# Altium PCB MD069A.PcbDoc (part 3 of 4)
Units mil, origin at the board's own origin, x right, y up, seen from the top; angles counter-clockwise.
Board outline 4569 x 3239 mil, 4 copper layers (Top Layer, Signal Layer 1, Signal Layer 2, Bottom Layer), stack 61.2 mil thick; 187 components, 103 nets, 560 pads, 220 vias.
Unrouted connection lines stored in the file: 7.
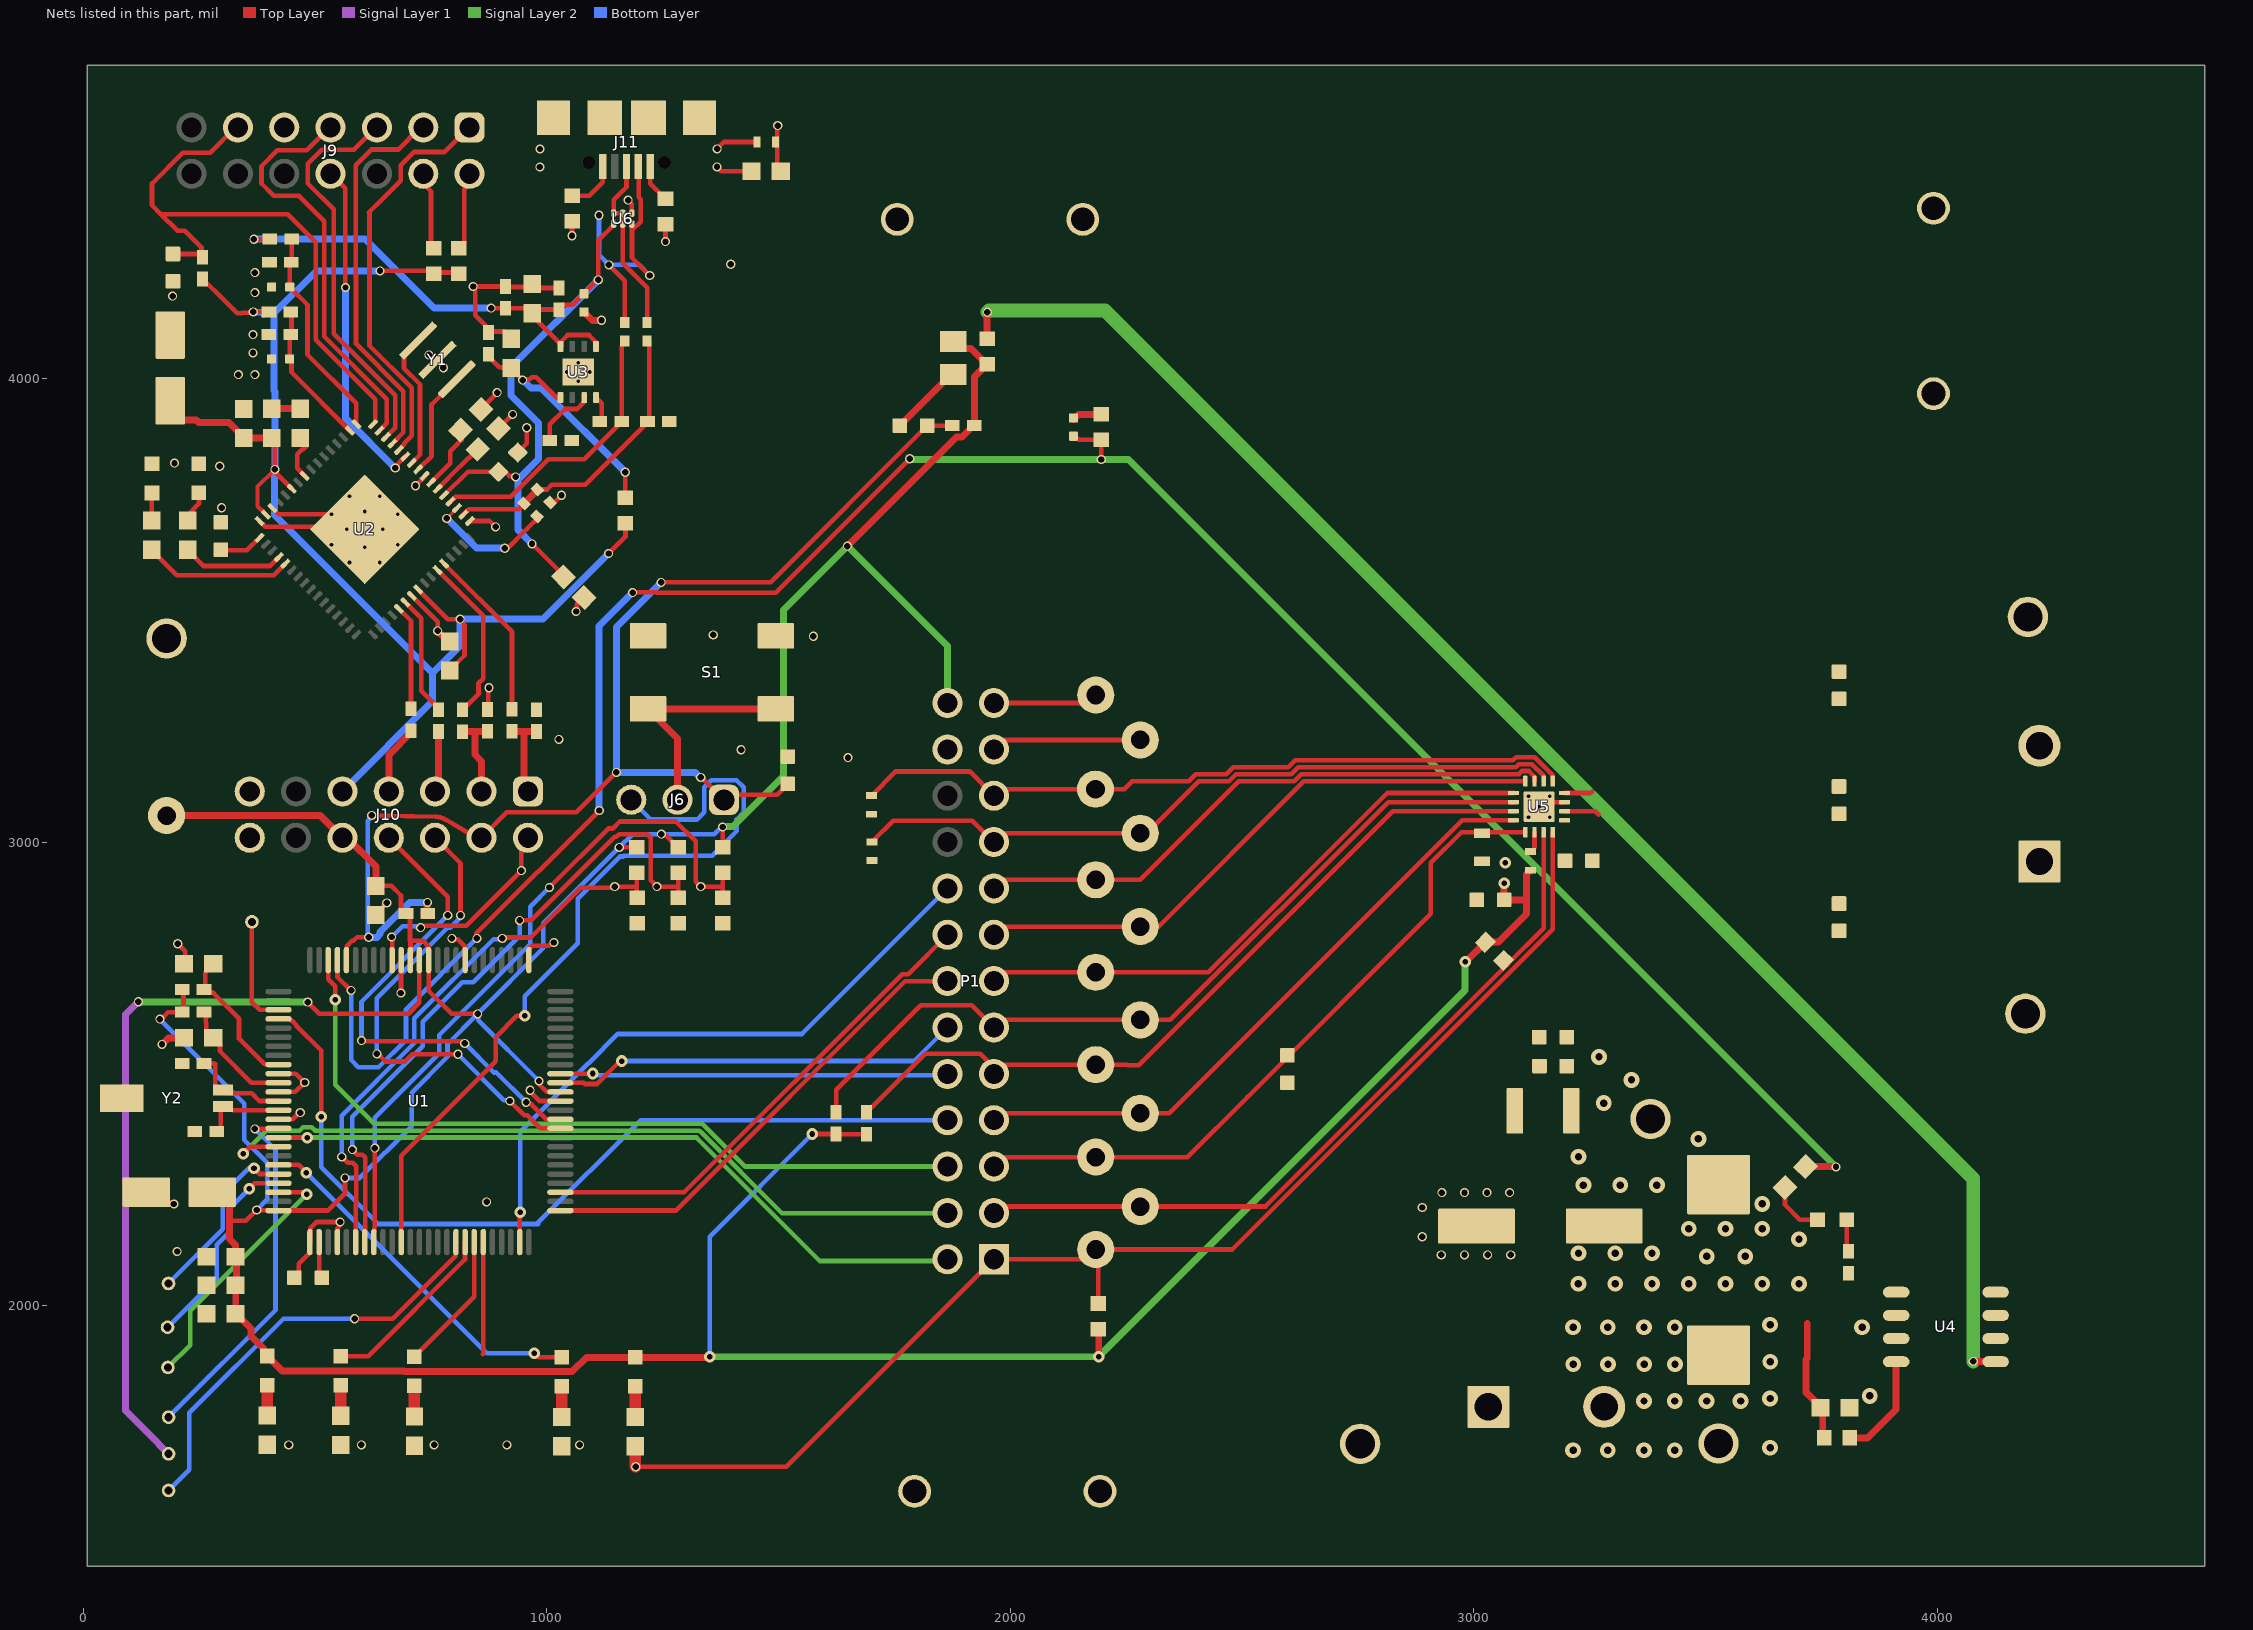
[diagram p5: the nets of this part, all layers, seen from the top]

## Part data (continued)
R58: library part CMP-0025924-5, "RES, 470, 5%, 0.1 W, 0603", Manufacturer=Yageo, Power_W=100mW, Supplier Part Number 1=311-470GRCT-ND, TempCo="100 ppm/C", Tolerance_%=5%, Value2=0.1W, Value_Code=470R, ValueDisplayed=470
R61: library part CMP-0026021-3, "RES, 150 k, 1%, 0.063 W, AEC-Q200 Grade 0, 0402", Manufacturer=Vishay-Dale, Power_W=63mW, Supplier Part Number 1=541-150KLCT-ND, TempCo="100 ppm/C", Tolerance_%=1%, Value2=0.063W, Value_Code=150k
R72 R75: library part CMP-0026888-3, "RES, 27, 5%, 0.063 W, AEC-Q200 Grade 0, 0402", Manufacturer=Vishay-Dale, Power_W=63mW, Supplier Part Number 1=541-27JCT-ND, TempCo="200 ppm/C", Tolerance_%=5%, Value2=0.063W, Value_Code=27R0, ValueDisplayed=27
R76: library part CMP-0026085-3, "RES, 1.40 k, 1%, 0.063 W, AEC-Q200 Grade 0, 0402", Manufacturer=Vishay-Dale, Power_W=63mW, Supplier Part Number 1=541-1.40KLCT-ND, TempCo="100 ppm/C", Tolerance_%=1%, Value2=0.063W, Value_Code=1k40, ValueDisplayed=1.40k
R77: library part CMP-0026859-2, "RES, 1.0 M, 5%, 0.063 W, AEC-Q200 Grade 0, 0402", Manufacturer=Vishay-Dale, Power_W=63mW, Supplier Part Number 1=541-1.0MJCT-ND, TempCo="200 ppm/C", Tolerance_%=5%, Value2=0.063W, Value_Code=1M00, ValueDisplayed=1.0M
R78: library part CMP-0026907-3, "RES, 33 k, 5%, 0.063 W, AEC-Q200 Grade 0, 0402", Manufacturer=Vishay-Dale, Power_W=63mW, Supplier Part Number 1=541-33KJCT-ND, TempCo="200 ppm/C", Tolerance_%=5%, Value2=0.063W, Value_Code=33k0, ValueDisplayed=33k
S1: library part CMP-0097347-1, "Tactile Switch SPST-NO Top Actuated Surface Mount", Coil Resistance_ohm=100mΩ, Contact Current Rating=50mA, Digikey Part Number=732-7022-1-ND, Manufacturer="Wurth Electronics", Mouser Part Number=710-430481025816, Operating Force=160gf, Operating Temperature Range="-40°C to +85°C"
SH-J1 SH-J2 SH-J3 SH-J4 SH-J5 SH-J6 SH-J7 SH-J8 SH-J9 SH-J10 SH-J11 SH-J12 SH-J19 SH-J29 SH-J31 SH-J32 SH-J33 SH-J34 SH-J36: library part CMP-0003761-2, "Shunt, 2.54mm, Gold, Black", Manufacturer="Wurth Elektronik", Supplier Part Number 1=732-2678-ND
TP1 TP2 TP3 TP4 TP5 TP6 TP7: library part CMP-0003719-1, "Testpoint", Manufacturer="Texas Instruments"
TP8 TP10: library part CMP-0055149-2, "Test Point, Multipurpose, White, TH", Color=White, Manufacturer="Keystone Electronics", Supplier Part Number 1=36-5012-ND
TP16 TP17 TP60: library part CMP-0075110-1, "1mm Uninsulated Shorting Plug, 10.16mm spacing, TH", Manufacturer=Harwin, PartNumber=D3082-05, Supplier Part Number 1=952-1873-ND
TP26: library part CMP-0055140-2, "Test Point, Miniature, Orange, TH", Color=Orange, Manufacturer="Keystone Electronics", Supplier Part Number 1=36-5003-ND
TP28 TP29 TP30 TP31 TP32 TP33 TP34 TP35 TP36 TP37 TP38 TP39 TP40: library part CMP-0055139-2, "Test Point, Miniature, White, TH", Color=White, Manufacturer="Keystone Electronics", Supplier Part Number 1=36-5002-ND
U1: library part CMP-0038879-1, "20 MHz Mixed Signal Microcontroller with 256 KB Flash, 18432 B SRAM and 74 GPIOs, -40 to 85 degC, 100-pin QFP (PZ), Green (RoHS & no Sb/Br)", Frequency(MHz)=20, Manufacturer="Texas Instruments", Temp Sensor=Yes
U2: library part CMP-0039269-4, "16-Bit Ultra-Low-Power Microcontroller, 128KB Flash, 8KB RAM, USB, 12Bit ADC, 2 USCIs, 32Bit HW MPY, RGC0064B (VQFN-64)", Alternate Manufacturer="Texas Instruments", Alternate PartNumber=MSP430F5528IRGCR, Frequency(MHz)=25, Operating Temperature Range="-40 to 85 C", Rating=Catalog, Temp Sensor=Yes
U3: library part CMP-0036328-3, "500mA, Adjustable, Low Quiescent Current, Low-Noise, High-PSRR, Single-Output LDO Regulator, DRB0008A (VSON-8)", Manufacturer="Texas Instruments", Operating Temperature Range="-40 to 125 C", Rating=Catalog
U4: library part CMP-0070570-1, "Ultra-Low Quiescent Current Voltage Regulator, 8-pin Narrow SOIC, Pb-Free", Manufacturer="Texas Instruments", PackageTopMarking=NSZXTT*LM903*6M-3, PowerWise=N
U5: library part CMP-0097573-1, "2-A Brushed DC Motor Driver with Stall Detection, Ripple Counting and Speed Regulation", Manufacturer="Texas Instruments", Max Supply Voltage=11V, Min Supply Voltage=1.65V, Operating Temperature Range="-40°C to +150°C", Switching Frequency=200kHz
U6: library part CMP-0043099-3, "Low-Capacitance 2-Channel +/-15kV ESD Protection Array for High-Speed Data Interfaces, DRY0006A (USON-6)", Breakdown Voltage(Min)(V)=11, IO Capacitance(Typ)(pF)=1.5, IO Leakage Current(nA)=1, Manufacturer="Texas Instruments", Operating Temperature Range="-40 to 85 C", Rating=Catalog
VM VSUP: library part CMP-0055147-2, "Test Point, Multipurpose, Red, TH", Color=Red, Manufacturer="Keystone Electronics", Supplier Part Number 1=36-5010-ND
Y1: library part CMP-0085483-1, "Oscillator, 4 MHz, 700 ppm, 39 pF, SMD", Frequency_Fixed=4MHz, Frequency Tolerance="700 ppm", Load Capacitance="39 pF", Manufacturer=MuRata
Y2: library part CMP-0004566-4, "Crystal, 32.768 kHz, 12.5pF, SMD", Alternate Manufacturer="Wurth Electronics", Alternate PartNumber=830025159, Frequency Tolerance="20 ppm", Frequency_Fixed=32.768kHz, Load Capacitance="12.5 pF", Manufacturer="Micro Crystal AG", Supplier Part Number 1=94M8466
ZZ1: library part CMP-0077236-1
ZZ2: library part CMP-0077237-1
ZZ3: library part CMP-0077238-1
ZZ4: library part CMP-0003616-3

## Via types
v1: diameter 19.68, hole 13.78, Top Layer to Bottom Layer, tented both sides, 133 vias
v2: diameter 34, hole 16, Top Layer to Bottom Layer, tented both sides, 47 vias
v3: diameter 25/25/25/25 (per signal layer), hole 12, Top Layer to Bottom Layer, 19 vias
v4: diameter 19.68, hole 7.87, Top Layer to Bottom Layer, 16 vias
v5: diameter 19.68, hole 7.87, Top Layer to Bottom Layer, tented both sides, 5 vias

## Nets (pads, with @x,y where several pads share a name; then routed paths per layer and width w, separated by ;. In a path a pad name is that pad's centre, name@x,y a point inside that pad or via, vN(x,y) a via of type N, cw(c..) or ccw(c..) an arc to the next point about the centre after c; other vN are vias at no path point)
A0: P1.19 R8.2 TP37.1 U5.10 | length 1579.1
  Top Layer w10: R8.2@1701.01,3000.93 1747.05,3046.97 1918.02,3046.97 P1.19@1964.3,3000.7 1983.33,3019.73 TP37.1@2280.18,3019.73 2293.85,3019.73 2406.28,3132.17 2471.63,3132.17 2486.63,3147.17 2605.79,3147.17 2620.79,3162.17 3090.2,3162.17 3097.01,3168.98 3124.85,3168.98 3150.3,3143.53 U5.10@3150.3,3132.17
A1: P1.21 R10.2 TP38.1 U5.9 | length 1576.2
  Top Layer w10: R10.2@1700.67,3100.69 1753.06,3153.07 1911.92,3153.07 P1.21@1964.3,3100.7 1978.49,3114.89 TP38.1@2183.57,3114.89 2245.13,3114.89 2262.41,3132.17 2385.07,3132.17 2400.07,3147.17 2465.42,3147.17 2480.42,3162.17 2599.57,3162.17 2614.57,3177.17 3083.99,3177.17 3090.8,3183.98 3131.06,3183.98 3169.98,3145.05 U5.9@3169.98,3132.17
ENABLE: U1.45 | length 242.7
  Top Layer w10: 862.05,1895.51 862.95,1896.41 U1.45@862.95,2137.87
EZFET_AVBUS: C24.2 R56.1 R61.2 U2.1 | length 460.2
  Top Layer w10: R56.1@449.36,4301.26 449.36,4251.97 445.4,4248.02 C24.2@445.4,4197.93 483.64,4159.68 483.64,4052.32 588.83,3947.13 U2.1@588.83,3902.1
EZFET_AVCC2ADC: C22.2 R55.1 R60.2 U2.2 | length 312.5
  Top Layer w10: R55.1@447.69,4144.57 449.02,4143.24 449.02,4096.99 444.96,4092.94 C22.2@444.96,4043.12 449.02,4039.07 449.02,4014.07 U2.2@574.91,3888.18
EZFET_D_N: C42.1 R72.2 U2.52 | length 613.9
  Top Layer w10: U2.52@792.05,3735.07 802.99,3746 922.1,3746 1002.59,3826.49 1080.35,3826.49 C42.1@1161.52,3907.66 1161.52,4071.53 R72.2@1167.94,4077.95
EZFET_D_P: C43.1 R75.2 R76.1 R77.2 U2.50 | length 662.5
  Top Layer w10: U2.50@819.89,3707.23 831.67,3719 939,3719 R76.1@951,3731 ; R77.2@979.43,3761.27 1000.2,3761.27 1010.57,3771.64 1082.64,3771.64 C43.1@1220,3909 ; R75.2@1216,4083 1221.01,4077.99 C43.1@1221.01,3907.66
  Top Layer w15: R76.1@950.97,3731.25 979,3759.28 R77.2@979,3762
EZFET_LED0: R58.1 U2.20 | length 219.7
  Top Layer w10: R58.1@225.05,3631.48 225.05,3630.5 259.15,3596.4 402.84,3596.4 U2.20@421.8,3615.36
EZFET_LED1: R59.1 U2.21 | length 322.2
  Top Layer w10: R59.1@147.47,3631.44 147.47,3630.46 201.82,3576.1 410.38,3576.1 U2.21@435.72,3601.44
EZFET_PUR: R76.2 U2.51 | length 282.9
  Top Layer w6: v1(784.09,3698.93) 805.97,3720.81 U2.51@805.97,3721.34
  Top Layer w10: v1(909,3634.64) 915.6,3634.64 957,3676.03 R76.2@981.59,3700.62
  Bottom Layer w15: v1(784.09,3698.93) 848.39,3634.64 v1(909,3634.64)
EZFET_RST: C23.2 J9.11 R57.1 U2.64 | length 1315.2
  Top Layer w10: C23.2@193.39,4269.42 250.7,4269.42 R57.1@257.39,4262.73 254.8,4265.32 254.8,4283.48 218.88,4319.4 203.25,4319.4 167.33,4355.31 ; J9.11@333.43,4542.4 328.31,4542.4 273.67,4487.76 214.64,4487.76 148.19,4421.31 148.19,4374.45 167.33,4355.31 ; U2.64@629.64,3907.11 629.64,3955.86 501.52,4083.99 501.52,4294.87 441.07,4355.31 167.33,4355.31
EZFET_TCK: J9.7 U2.63 | length 899.5
  Top Layer w10: J9.7@529.76,4540.24 482.32,4492.8 418.18,4492.8 384.4,4459.03 384.4,4421.46 410.97,4394.89 464.38,4394.89 519.39,4339.88 519.39,4091.39 654.78,3956 654.78,3904.22 U2.63@638.94,3888.38
EZFET_TDI: J9.3 U2.61 | length 820.7
  Top Layer w10: U2.61@671.5,3865.26 690.53,3884.29 690.53,3973.19 588.33,4075.39 588.33,4223.81 588.07,4224.06 588.07,4461.19 621.53,4494.65 679.2,4494.65 724.8,4540.24 J9.3@729.76,4540.24
EZFET_TDO: J9.1 U2.60 | length 870.4
  Top Layer w10: U2.60@680.7,3846.62 692.58,3858.51 692.58,3861.06 708.4,3876.89 708.4,3980.6 617.28,4071.72 617.28,4358.05 616.32,4359.01 646.16,4388.84 684.4,4427.09 684.4,4461.01 712.65,4489.26 778.77,4489.26 J9.1@829.76,4540.24
EZFET_TEST: J9.8 U2.59 | length 726
  Top Layer w10: J9.8@533.43,4442.4 565,4410.83 v1@565,4197 ; v1(672.79,3807.8) 672.79,3810.87 694.52,3832.6 U2.59@694.62,3832.7
  Bottom Layer w15: v1(565.61,4197) 565.61,3914.98 v1(672.79,3807.8)
EZFET_TMS: J9.5 U2.62 | length 852.8
  Top Layer w10: J9.5@629.76,4540.24 583.77,4494.26 514.42,4494.26 484.4,4464.23 484.4,4421.46 539.92,4365.94 539.92,4096.92 672.65,3964.19 672.65,3894.25 U2.62@652.86,3874.46
EZFET_UARTRXD: R66.1 U2.38 | length 254.2
  Top Layer w10: U2.38@699.43,3513.11 729.16,3483.38 729.16,3327.09 765.89,3290.36 R66.1@765.89,3286.42
EZFET_UARTTXD: R67.1 U2.37 | length 227
  Top Layer w10: U2.37@680.7,3504.2 706.91,3477.99 R67.1@706.91,3288
EZFET_USB_Shield: C47.1 J11.Shell R78.2 | length 181.9
  Top Layer w10: v1(1367,4457.41) 1376.38,4448.03 C47.1@1453,4448.03 ; v1(1367.15,4496.16) 1381.99,4511 R78.2@1453,4511
  other v1: 985,4457 985.15,4495.75
EZFET_V18: C28.1 U2.55 | length 140.3
  Top Layer w10: U2.55@750.29,3777.02 791.3,3817.94 791.3,3843.64 803,3855.34 815.89,3868.23 813.66,3870.46 C28.1@813.66,3889.21
EZFET_VBUS: C20.2 C21.1 C35.1 C36.1 C37.1 C48.2 L1.2 R56.2 U2.53 U3.5 U3.8 U6.1 | length 2228.6
  Top Layer w10: v1(367.89,4301.28) R56.2@398.15,4301.28 ; U2.53@778.13,3749.18 829.98,3799.33 910.6,3799.33 919.44,3790.49 930.76,3790.49 v1(932.61,3788.63) ; v1(879.84,4152.63) C35.1@907.4,4152.63 ; C35.1@910.39,4151.98 957.8,4151.98 C36.1@968.11,4141.67 969.17,4142.74 C36.1@974.92,4142.74 ; v1(967.96,3644) C21.1@1041.59,3570.37 ; U3.8@1029.31,4069.89 1030.41,4070.99 1030.41,4080.38 1044.61,4094.57 1090.78,4094.57 1104.98,4080.38 1104.98,4070.99 U3.5@1106.08,4069.89 ; U3.8@1029.31,4075.6 981.81,4123.1 981.81,4135.85 C36.1@974.92,4142.74 ; U6.1@1144.03,4334.75 1143.13,4333.85 1143.13,4330.89 1110.83,4298.6 v1(1110.83,4213.6) 1109.91,4213.6 1055.87,4159.56 1033.06,4159.56 1026.24,4152.75 C37.1@1026.24,4148.81 1025.51,4149.55 981.73,4149.55 C36.1@974.92,4142.74 ; v1(1255.92,4296.14) L1.2@1255.92,4329.25
  Bottom Layer w15: v1(367.89,4301.28) 607.38,4301.28 756.03,4152.63 v1(879.84,4152.63) ; v1(932.61,3788.63) v1@938.19,3783.05 ; v1(967.96,3644) 938.19,3673.77 v1@938.19,3783.05 ; v1(1110.83,4213.6) 922.39,4025.16 922.39,3964.54 981.9,3905.04 981.9,3826.76 v1@938.19,3783.05
EZFET_VCC: C31.2 C32.1 C33.1 C34.1 J10.9 R55.2 R57.2 R62.2 R63.2 R68.1 U2.11 U2.15 U2.40 | length 3248.3
  Top Layer w9: U2.15@393.96,3707.23 376.06,3725.12 376.06,3767.67 v1(413.25,3804.86)
  Top Layer w10: R57.2@257.39,4215.49 302.5,4170.38 303.28,4170.38 331.79,4141.87 341.79,4141.87 342.63,4142.72 364.73,4142.72 v1(366.58,4144.57) R55.2@396.5,4144.57 ; v1(413.25,3804.86) C32.1@413.25,3872.61 ; v1@415.1,3797.44 U2.11@449.63,3762.9 ; v1(640,4233) 749.76,4233 R62.2@756.08,4226.68 756.65,4226.11 761.71,4226.11 765.13,4229.53 806.74,4229.53 R63.2@809.84,4226.43 ; U2.40@727.27,3540.94 786.47,3481.74 v1(812.86,3481.74) 812.86,3479.12 822.29,3469.69 822.29,3403.19 C34.1@793.67,3374.56 ; v1@1133.28,3623.53 1169.5,3659.74 R68.1@1169.5,3688.8
  Top Layer w15: C31.2@187.54,3952.77 187.54,3934.97 211.54,3910.97 243.64,3910.97 249.04,3905.57 313.95,3905.57 346.36,3873.16 C33.1@346.36,3872.17 346.58,3872.39 406.29,3872.39 C32.1@406.51,3872.61
  Bottom Layer w15: v1(366.58,4144.57) 367.48,4143.68 385.62,4143.68 388.91,4140.38 390.4,4141.87 411.61,4141.87 ; v1@412.19,3804.86 412.19,3706.59 753.69,3365.09 ; v1(413.25,3804.86) 413.25,3973.18 411.61,3974.82 411.61,4141.87 ; J10.9@559,3110.02 753.69,3304.71 753.69,3365.09 ; v1(640,4233) 502.74,4233 411.61,4141.87 ; v1(1133.28,3623.24) 991.78,3481.74 v1(812.86,3481.74) 812.86,3424.26 753.69,3365.09
EZFET_Vcore: C29.2 U2.17 | length 94.9
  Top Layer w10: C29.2@296.85,3631.18 297.95,3630.07 353,3630.07 U2.17@380.04,3657.12
EZFET_VREF: C25.1 U2.9 | length 104.8
  Top Layer w10: C25.1@467.95,3872.61 481.65,3858.91 481.65,3856 482.35,3855.3 474.81,3847.76 472.01,3847.76 461.42,3837.17 461.42,3806.8 U2.9@477.47,3790.74
EZFET_VUSB: C30.1 U2.54 | length 121.4
  Top Layer w10: U2.54@764.21,3763.1 812.07,3810.87 C30.1@850.84,3848.16
EZFET_XT2IN: U2.57 Y1.1 | length 222.2
  Top Layer w10: U2.57@727.27,3809.48 751.21,3833.42 751.21,3944.62 Y1.1@805.78,3999.19
EZFET_XT2OUT: U2.58 Y1.3 | length 298.5
  Top Layer w10: U2.58@708.54,3818.58 708.54,3818.97 726.28,3836.71 726.28,3988 691.64,4022.64 691.64,4052.08 Y1.3@722.26,4082.7
GND: C1.1 C2.1 C3.1 C4.1 C6.2 C7.2 C8.1 C15.2 C20.1 C21.2 C22.1 C23.1 C24.1 C25.2 C26.1 C27.1 C28.2 C29.1 C30.2 C31.1 C32.2 C33.2 C34.2 C35.2 C36.2 C37.2 C38.2 C39.2 C40.2 C41.1 C42.2 C43.2 C44.1 C45.2 C46.1 C47.2 C48.1 C49.1 C50.2 C51.1 C52.2 C53.2 C54.2 C55.2 C56.1 C57.1 C58.1 C59.1 C60.1 D1.1 D2.1 GND.1 J8.1 J9.9 J10.13 J10.14 L2.2 P1.24 R2.2 R8.1 R10.1 R11.1 R35.1 R42.1 R43.1 R45.1 R47.1 R51.2 R52.2 R53.2 R60.1 R61.1 R77.1 R78.1 S1.3 S1.4 TP16.1 TP16.2 TP17.1 TP17.2 TP24.1 TP60.1 TP60.2 U1.10 U1.12 U1.15 U1.26 U1.29 U1.63 U1.76 U1.83 U1.90 U2.14 U2.16 U2.39 U2.49 U2.56 U2.65 U3.4 U3.9 U4.2 U4.3 U4.4 U4.5 U4.6 U4.7 U5.7 U5.17 U6.4 Y1.2 Y2.3 | length 2757.2
  Top Layer w10: v1(203.63,2781.31) 220.06,2764.88 C15.2@220.06,2738.54 ; U2.16@380.04,3693.31 392.35,3681 507,3681 U2.65@534,3708 ; U2.14@407.88,3721.15 420,3709.02 421,3708 U2.65@534,3708 ; U1.15@421.02,2402.63 421.37,2402.98 451.36,2402.98 465.38,2417 v1(468,2417) ; U1.12@421.02,2461.69 457.48,2461.69 v1(477.73,2481.94) 458.62,2501.06 U1.10@421.02,2501.06 ; C49.1@455.41,2060.9 464.6,2070.09 464.6,2090.89 488.35,2114.64 488.35,2137.27 489.28,2138.21 489.28,2167.72 502.56,2181 v1(554,2181) 552.15,2179.15 552.15,2171.53 548.34,2167.72 548.34,2138.21 U1.29@547.99,2137.87 ; U2.65@536,3708 U2.65@534,3708 ; C54.2@630.92,2851.07 636.2,2851.07 v1(654.65,2869.51) ; v1(685,2675) 685.44,2675.44 685.44,2745.79 U1.90@685.79,2746.13 ; U2.39@708.54,3531.84 764.44,3475.94 v1(764.44,3456.19) ; v1(716.63,3769.36) 736.37,3789.11 U2.56@736.37,3790.94 ; v1(745.32,4051.62) 760.01,4036.93 763.94,4036.93 v1(776.82,4024.06) ; v1(795,2793) 796.85,2791.15 808.08,2791.15 823.24,2775.99 823.24,2746.48 U1.83@823.58,2746.13 ; U2.49@833.81,3693.31 876.77,3693.31 v1(889.43,3680.66) ; v1(840.84,4199.19) C35.2@910.39,4199.23 C35.2@910.39,4199.23 911.58,4198.04 966.86,4198.04 966.86,4203.42 C36.2@968.11,4204.66 968.11,4196.79 968.85,4196.05 C37.2@1026.24,4196.05 ; v1@845.32,4197.95 v1@845.32,4199.19 ; v1@845.35,4197.95 845.35,4137.48 873.88,4108.95 C40.2@873.88,4100.09 ; C28.2@852.64,3928.19 852.64,3930.14 v1(892.79,3970.29) ; C27.1@871.56,3286.62 873.62,3288.68 873.62,3332.09 v1(875.13,3333.6) ; C40.2@876.09,4102.3 908.06,4102.3 922.83,4087.54 C38.2@922.83,4086.55 ; C30.2@889.84,3887.12 v1(926.12,3923.39) ; C20.1@937.16,3841.09 956.69,3860.62 v1(956.69,3894.59) ; U1.76@961.38,2746.13 961.72,2746.48 961.72,2770.56 968.14,2776.98 1005.36,2776.98 1012.38,2784 v1(1015,2784) ; v1(963.9,2465.44) 963.9,2462.82 969.73,2456.98 969.73,2456.89 984.62,2442 U1.63@1029.29,2442 ; R77.1@1010.05,3730.65 1013.22,3730.65 v1(1031.49,3748.92) ; v1(1054.16,4308.62) 1054.16,4335.07 L2.2@1054.9,4335.81 ; v1(1063,3498) 1064.85,3499.85 1064.85,3513.9 1084,3533.04 C21.2@1084,3534 ; U3.4@1106.08,3959.65 1118,3947.73 C42.2@1118,3907 ; v1(1175.24,4385.46) 1183.4,4377.29 U6.4@1183.4,4357.39 ; C47.2@1496.62,4448.03 1496.62,4544.82 v1(1498,4546.19) ; v5(3140.46,3077.05) 3150.3,3086.89 U5.7@3195.57,3086.89
  Top Layer w15: C51.1@136.11,2245.41 160.11,2221.41 192.44,2221.41 193.99,2219.86 v1(195.25,2219.86) ; v1(169.75,2564.27) 183.73,2578.26 217,2578.26 C50.2@217.14,2578.4 ; C32.2@406.51,3935.6 C25.2@467.95,3935.6 ; v1(764.44,3456.19) 764.44,3455.96 C34.2@790.72,3429.68 ; C48.1@1080,4144.31 1097.99,4126.32 v1(1117.95,4126.32) ; C59.1@1768,3900 1768,3905.53 1855.7,3993.23 1855.7,3994.28 1873.72,4012.29 C7.2@1876.75,4012.29 ; C60.1@2136,3911.89 2147.11,3923 R35.1@2196,3923
  other v1: 443.05,1700.33 599.93,1700.33 756.8,1700.33 913.68,1700.33 1070.55,1700.33 2929.51,2110.26 2979.51,2110.26 3029.51,2110.26 3079.51,2110.26 202.42,2117.39 2888.51,2149.26 2888.51,2212.26 870.07,2224.49 2930.92,2244.53 2979.59,2244.53 3028.25,2244.53 3076.92,2244.53 1649.56,3182.96 1418.99,3199.88 1025.9,3222.11 1574.98,3444.66 1358.86,3447.68 298.25,3722.05 294.34,3811.53 196.74,3818.09 334.57,4009 370,4009 366.13,4056.01 366.13,4095.37 192.63,4178.37 370.07,4185.93 370.07,4229.24 1396.61,4247.27
  other v2: 3853.95,1805.95 3837.38,1954
  other v3: 3067.69,2955.69
  other v4: 574.07,3603.67 639.77,3603.67 606.92,3636.52 535.38,3642.36 678.47,3642.36 568.23,3675.21 645.62,3675.21 535.38,3708.06 678.47,3708.06 606.92,3713.91 574.07,3746.76 639.77,3746.76 1067.69,3995.09 1043.09,4014.77 1092.3,4014.77 1067.69,4034.46
  other v5: 3117.62,3054.22 3163.29,3054.22 3117.62,3099.88 3163.29,3099.88
GUI_STATUS: D8.2 U1.44 | length 298.6
  Top Layer w10: D8.2@719.51,1890.5 719.51,1895.74 843.27,2019.51 U1.44@843.27,2137.87
ID1: R39.2 R51.1 U1.31 | length 1220.2
  Top Layer w10: v1(557.56,2321.56) 570.59,2308.53 581.5,2308.53 588.72,2301.32 588.72,2220.59 587.36,2219.24 U1.31@587.36,2137.87 ; v1(903.72,2793) 905.57,2794.85 965.38,2794.85 1072.99,2902.47 1144.49,2902.47 v1(1146.5,2904.48) 1191.25,2904.48 1194.18,2907.41 ; R39.2@1194.18,2934.17 1194.18,2907.41 ; R51.1@1194.54,2880.29 1194.18,2880.65 1194.18,2907.41
  Bottom Layer w10: v1(557.56,2321.56) 557.56,2410.72 714.11,2567.26 714.11,2620.38 884.88,2791.15 901.86,2791.15 v1(903.72,2793)
ID2: R40.2 R52.1 U1.32 | length 1451
  Top Layer w10: v1(580.28,2337.17) 591.04,2326.41 602.09,2326.41 607.95,2320.55 607.95,2161.9 607.05,2160.99 U1.32@607.05,2137.87 ; v1(941.28,2831.72) 966.56,2831.72 1146.84,3012.01 1150.25,3012.01 1156.15,3017.91 1216.24,3017.91 1223.79,3010.37 1223.79,2918.04 v1(1237.35,2904.48) 1280.21,2904.48 1283.18,2907.45 ; R40.2@1283.18,2934.17 1283.18,2907.45 ; R52.1@1283.61,2880.29 1283.18,2880.72 1283.18,2907.45
  Bottom Layer w10: v1(580.28,2337.17) 580.28,2408.16 731.98,2559.86 731.98,2612.97 817.29,2698.28 841.13,2698.28 941.28,2798.44 v1(941.28,2831.72)
ID3: R41.2 R53.1 U1.33 | length 1518.9
  Top Layer w10: U1.33@626.73,2137.87 626.73,2160.99 627.64,2161.9 627.64,2168.28 628.86,2169.5 v1(628.86,2340.54) ; v1(1005.35,2902.65) 1132.59,3029.88 1142.28,3029.88 1157.51,3045.11 1278.05,3045.11 1321,3002.16 1321,2915.45 v1(1331.97,2904.48) 1376.41,2904.48 1379.34,2907.41 ; R41.2@1379.34,2934.17 1379.34,2907.41 ; R53.1@1379.69,2880.29 1379.34,2880.64 1379.34,2907.41
  Bottom Layer w10: v1(628.86,2340.54) 628.86,2406.03 767.73,2544.9 767.73,2584.47 963.99,2780.74 963.99,2861.29 v1(1005.35,2902.65)
IN1: P1.13 TP34.1 U5.13 | length 1289.2
  Top Layer w10: P1.13@1964.3,2700.7 1983.46,2719.86 TP34.1@2184.18,2719.86 2291.44,2719.86 2426.62,2719.86 2813.34,3106.58 U5.13@3085.34,3106.58
IN2: P1.15 TP35.1 U5.12 | length 1283.9
  Top Layer w10: P1.15@1964.3,2800.7 1982.02,2818.42 TP35.1@2280.18,2818.42 2319.46,2818.42 2633.21,3132.17 U5.12@3110.93,3132.17
IPROPI: C3.2 P1.5 R2.1 TP30.1 U5.1 | length 1509.6
  Top Layer w10: P1.5@1964.3,2300.7 1984.74,2321.14 TP30.1@2184.18,2321.14 2381.9,2321.14 2511.6,2450.83 2906.85,2846.08 2906.85,2955.68 2973.1,3021.93 3027.97,3021.93 U5.1@3110.93,3021.93
MCU_3V3: C2.2 C7.1 C46.2 C51.2 C52.1 C53.1 C54.1 D5.2 D11.2 J10.10 P1.26 R1.1 R4.1 R5.1 R6.1 R7.1 R9.2 R18.1 R19.2 R24.1 R37.1 R39.1 R40.1 R41.1 TP26.1 U1.25 U1.64 U1.87 U1.89 | length 9867.1
  Top Layer w10: v1(165.14,2618.88) 167.76,2618.88 182.6,2633.71 214.63,2633.71 216.06,2635.14 216.06,2682.72 R9.2@215.75,2683.03 ; 317.79,2183.47 350.47,2183.47 v1(374,2207) 374.87,2206.13 420.68,2206.13 U1.25@421.02,2205.78 527.08,2205.78 564.62,2243.32 v1(564.62,2276.13) ; C54.1@630.92,2906.18 664.62,2906.18 685.3,2885.51 685.3,2853.3 692.11,2846.49 R18.1@696.05,2846.49 704.86,2846.49 704.86,2787.55 ; U1.89@705.47,2746.13 705.82,2746.48 705.82,2784.54 708.83,2787.55 732.94,2787.55 744.5,2775.99 744.5,2745.64 744.84,2745.3 744.84,2679.5 794.39,2629.95 v1(850.61,2629.95) ; v1(983.03,2485.28) 984.88,2483.43 984.88,2476.58 999.43,2462.03 1028.94,2462.03 U1.64@1029.29,2461.69 ; v1(1156.25,2989.29) R39.1@1194.18,2989.29 ; v1(1247.04,3017.91) 1248.9,3016.06 1255.43,3016.06 1282.2,2989.29 R40.1@1283.18,2989.29 ; v1(1379.26,3033.3) 1379.26,2989.37 R41.1@1379.34,2989.29 ; v3@1572.21,2371.3 v3(1572.52,2370.99) R6.1@1624.16,2370.99 1624.41,2370.74 R7.1@1689.93,2370.74
  Top Layer w15: TP26.1@162.44,3057.87 TP26.1@179.7,3057.87 511.14,3057.87 J10.10@559,3010.02 569.27,3010.02 630.92,2948.37 C54.1@630.92,2906.18 ; C51.2@277.84,2245.41 291.6,2245.41 315.6,2221.41 315.6,2144.31 328.36,2131.55 C53.1@328.36,2106.08 ; C46.2@328.52,1983.23 329.5,1983.23 361.62,1951.11 361.62,1935.52 388.54,1908.6 388.54,1900.22 D5.2@396.79,1891.97 429.14,1859.63 691.89,1859.63 692.89,1858.63 742.02,1858.63 742.28,1858.37 1054.16,1858.37 1085.02,1889.23 1349.99,1889.23 v3(1351.15,1890.4) ; C53.1@328.52,2105.92 C53.1@328.36,2106.08 ; C46.2@328.79,1983.23 328.79,2044.04 C52.1@328.52,2044.31 330.23,2046.02 330.23,2104.21 C53.1@328.36,2106.08 ; v1(1648.26,3639.3) 1883.79,3874.83 1895.84,3874.83 1920.16,3899.14 R19.2@1922.16,3899.14 ; C7.1@1876.75,4077.41 1889.01,4065.14 1915.32,4065.14 1949.44,4031.01 1949.44,4030.46 1948.03,4030.46 1922.16,4004.59 R19.2@1922.16,3903.45 ; R24.1@2189.37,1950.07 2190.54,1948.9 v3(2190.54,1890.78) ; v3(2981.29,2742.82) 2982.69,2742.82 R1.1@3024.46,2784.59 ; R1.1@3023.92,2784.85 3052.99,2784.85 3113.59,2845.45 3113.59,2879.6 ; v3(3065.07,2912.07) C2.2@3065.07,2875.94 3109.93,2875.94 3113.59,2879.6 ; R5.1@3121.71,2939.91 3113.59,2931.79 3113.59,2879.6
  Signal Layer 2 w15: v3(1351.15,1890.4) 2190.15,1890.4 v3(2190.54,1890.78) 2980.75,2680.99 v3@2980.75,2743.08 ; v1(1379.26,3033.3) 1380.15,3034.19 1401.47,3034.19 1510.78,3143.5 1510.78,3501.82 v1@1647,3638.04 ; v1(1648.26,3639.3) 1864.3,3423.26 P1.26@1864.3,3300.7
  Bottom Layer w10: v1(165.14,2618.88) 347.28,2436.74 347.28,2357.94 396.72,2308.51 396.72,2229.72 v1(374,2207) ; v1(564.62,2276.13) 596.57,2276.13 708.28,2387.84 708.28,2460.17 785.6,2537.49 785.6,2564.94 v1(850.61,2629.95) ; v1(983.03,2485.28) 851.76,2616.55 851.76,2628.8 v1(850.61,2629.95) ; v3(1351.15,1890.4) 1351.15,2149.63 v3(1572.52,2370.99) ; v1(1379.26,3033.3) 1376.64,3033.3 1361.25,3017.91 v1(1247.04,3017.91) 1184.87,3017.91 v1(1156.25,2989.29) 992.28,2825.32 992.28,2772.26 850.61,2630.58 v1(850.61,2629.95)
MCU_STATUS: D6.2 U1.43 | length 395.6
  Top Layer w10: D6.2@551.98,1891.5 614.62,1891.5 823.24,2100.11 823.24,2137.52 U1.43@823.58,2137.87
MCU_UARTRXD: J10.8 U1.61 | length 1068.3
  Top Layer w10: v1(600.11,2572.24) 601,2571.34 815.26,2571.34 820.1,2566.5 v1(822.72,2566.5) ; J10.8@659,3010.02 786.18,2882.84 v1(786.18,2842.63) ; v1(955.2,2439.29) 957.06,2437.44 963.91,2437.44 998.37,2402.98 1028.94,2402.98 U1.61@1029.29,2402.63
  Bottom Layer w10: v1(600.11,2572.24) 600.11,2656.55 786,2842.45 v1@786,2844 ; v1(822.72,2566.5) 885.67,2503.55 890.95,2503.55 v1(955.2,2439.29)
MCU_UARTTXD: J10.6 U1.60 | length 1040.5
  Top Layer w10: v1(633.22,2543.78) 635.5,2543.78 651.93,2527.35 693.45,2527.35 709.1,2543 v1(808.32,2543) ; J10.6@759,3010.02 813.74,2955.28 v1(813.74,2842.63) ; v1(920.18,2442.18) 951.21,2411.16 957.55,2411.16 985.75,2382.96 U1.60@1029.28,2382.96
  Bottom Layer w10: v1(633.22,2543.78) 633.22,2663.35 785.59,2815.72 791.39,2815.72 811.89,2836.21 811.89,2838.15 v1@814,2840.27 ; v1(808.32,2543) 907.28,2444.04 918.33,2444.04 v1(920.18,2442.18)
MSP_IN1: P1.14 U1.51 | length 1040
  Top Layer w10: U1.51@1029.29,2205.78 1277.75,2205.78 1772.67,2700.7 P1.14@1864.3,2700.7
MSP_IN2: P1.16 U1.53 | length 1065.1
  Top Layer w10: U1.53@1029.29,2245.15 1106.65,2245.15 1295.91,2245.15 1766.45,2715.7 1779.3,2715.7 P1.16@1864.3,2800.7
MSP_IPROPI: P1.6 U1.98 | length 1669.1
  Top Layer w10: U1.98@528.31,2746.13 528.31,2704.78 543.67,2689.42 v3(543.67,2660.23)
  Signal Layer 2 w10: v3(543.67,2660.23) 543.67,2477.1 627.51,2393.26 1335.14,2393.26 1427.71,2300.7 P1.6@1864.3,2300.7
MSP_nFAULT: P1.2 U1.17 | length 1556.1
  Top Layer w10: U1.17@421.02,2363.26 v3(483.13,2363.26) v3@483.87,2363.99
  Signal Layer 2 w10: v3(483.13,2363.26) 1322.72,2363.26 1588.98,2097 1860.6,2097 P1.2@1864.3,2100.7
MSP_nSLEEP: P1.18 U1.49 | length 1378
  Top Layer w10: U1.49@941.69,2137.87 941.69,2201.64 v3(942.55,2202.5)
  Bottom Layer w10: v3(942.55,2202.5) 942.55,2376.2 1076.51,2510.16 1076.51,2510.76 1089.69,2523.94 1090.29,2523.94 1153.11,2586.76 1550.36,2586.76 P1.18@1864.3,2900.7
MSP_RC_OUT: P1.4 U1.18 | length 1702.6
  Top Layer w10: v3(344.86,2328.55) 359.89,2343.57 U1.18@421.02,2343.57
  Signal Layer 2 w10: v3(344.86,2328.55) 394.59,2378.27 466.32,2378.27 473.82,2385.76 492.45,2385.76 499.03,2379.19 499.33,2378.9 499.45,2378.81 499.57,2378.73 499.72,2378.65 499.92,2378.57 500.18,2378.49 500.51,2378.4 500.94,2378.33 501.47,2378.28 501.92,2378.27 502.24,2378.26 1328.93,2378.26 1331.86,2375.33 1507.18,2200.01 1863.61,2200.01 P1.4@1864.3,2200.7
MSP_SCL: P1.10 U1.66 | length 837.8
  Top Layer w10: U1.66@1029.29,2501.06 1098.63,2501.06 v3(1099.01,2501.44)
  Bottom Layer w10: v3(1099.01,2501.44) 1102.52,2497.93 1861.53,2497.93 P1.10@1864.3,2500.7
MSP_SDA: P1.12 U1.65 | length 886.4
  Top Layer w10: U1.65@1029.29,2481.37 1079.08,2481.37 1081.52,2478.94 1108.33,2478.94 1157.73,2528.34 v3(1161.59,2528.34)
  Bottom Layer w10: v3(1161.59,2528.34) 1791.94,2528.34 P1.12@1864.3,2600.7
MSP_VREF: P1.8 U1.4 | length 1869.9
  Top Layer w10: U1.4@421.02,2619.17 444.88,2619.17 448.66,2615.39 450.25,2615.39 459.57,2606.07 459.57,2604.48 512.96,2551.08 v3(512.96,2408.37)
  Bottom Layer w10: v3(512.96,2408.37) 512.96,2299.59 635.79,2176.76 980.86,2176.76 979.69,2177.93 1202.46,2400.7 P1.8@1864.3,2400.7
NetC15_1: C15.1 R9.1 U1.9 | length 314.6
  Top Layer w10: C15.1@283.05,2738.54 262.99,2718.49 262.99,2683.03 269.8,2676.22 279.54,2676.22 280.72,2675.04 335.94,2619.82 335.94,2576.31 391.17,2521.09 420.68,2521.09 U1.9@421.02,2520.74
NetC26_2: C26.2 J10.1 R64.2 | length 185.9
  Top Layer w15: R64.2@924.87,3239.66 950.95,3239.66 ; J10.1@959,3110.02 950.95,3118.07 950.95,3239.66 ; C26.2@977.55,3239.15 977.03,3239.66 950.95,3239.66
NetC27_2: C27.2 J10.3 R65.2 | length 188.8
  Top Layer w15: R65.2@818.39,3238.81 818.73,3239.15 871.33,3239.15 C27.2@871.56,3239.37 ; 844.51,3239.37 844.51,3189.38 859,3174.89 J10.3@859,3110.02
NetC38_1: C38.1 C40.1 R68.2 U3.1 | length 559.7
  Top Layer w10: C40.1@873.88,4052.85 873.88,4048.91 897.38,4025.42 902.3,4025.42 903.16,4024.55 921.84,4024.55 C38.1@922.83,4023.56 ; C38.1@922.83,4022.16 v1(947.61,3997.38) 949.46,3999.23 962.98,3999.23 967.45,4003.71 977.45,4003.71 1021.51,3959.65 U3.1@1029.31,3959.65 ; R68.2@1169.04,3743.91 v1(1169.04,3798.42)
  Bottom Layer w15: v1(947.61,3997.38) 948.88,3997.38 965.53,3980.73 987.31,3980.73 1169.04,3798.99 v1(1169.04,3798.42)
NetC39_1: C39.1 U3.3 | length 138.5
  Top Layer w10: C39.1@1006.09,3867.22 1006.09,3901.85 1039.2,3934.97 1065.19,3934.97 1080.49,3950.27 U3.3@1080.49,3959.65
NetC44_2: C44.2 U1.14 Y2.1 | length 182.4
  Top Layer w10: C44.2@287.52,2376.79 289.68,2376.79 296.5,2383.6 296.5,2425.5 Y2.1@299,2428 ; Y2.1@301.25,2430.28 308.06,2423.47 322.29,2423.47 323.76,2422 U1.14@423,2422
NetC45_1: C45.1 U1.13 Y2.2 | length 221
  Top Layer w10: C45.1@262.9,2522.82 263.24,2523.17 279.63,2523.17 280,2522.8 284.6,2522.8 284.6,2472.53 291.13,2466 Y2.2@301,2466 ; Y2.2@301.25,2465.72 308.06,2458.91 363.09,2458.91 380,2442 U1.13@421.02,2442
NetC49_2: C49.2 U1.27 | length 79.4
  Top Layer w10: U1.27@508.62,2137.87 508.97,2137.52 508.97,2066.4 C49.2@514.47,2060.9
NetC50_1: C50.1 R37.2 U1.11 | length 255.5
  Top Layer w10: R37.2@269.69,2626.78 263.83,2620.92 263.83,2612.64 265.45,2611.02 265.45,2592.1 276.02,2581.53 277,2581.53 C50.1@280.13,2578.4 ; C50.1@272.89,2578.4 281.11,2578.4 294.82,2564.7 294.82,2549.23 362.68,2481.37 U1.11@421.02,2481.37
NetD1_2: D1.2 R58.2 | length 69.7
  Top Layer w10: R58.2@225.05,3694.48 225.05,3706.15 249.42,3730.52 D1.2@249.42,3754.06
NetD2_2: D2.2 R59.2 | length 59.4
  Top Layer w10: R59.2@147.47,3694.43 D2.2@147.47,3753.85
NetD4_1: D4.1 R11.2 | length 68.8
  Top Layer w10: D4.1@3804.14,2186.22 3804.14,2119.99 R11.2@3805.99,2118.14
NetD5_1: D5.1 R42.2 | length 65.4
  Top Layer w25: R42.2@396.5,1763.71 396.65,1763.85 396.65,1828.84 D5.1@396.79,1828.98
NetD6_1: D6.1 R43.2 | length 65.2
  Top Layer w25: R43.2@555.4,1763.23 D6.1@555.36,1828.5
NetD8_1: D8.1 R45.2 | length 66.2
  Top Layer w25: R45.2@714.29,1761.23 D8.1@714.26,1827.5
NetD10_1: D10.1 R47.2 | length 66.2
  Top Layer w25: R47.2@1032.08,1760.23 D10.1@1032.08,1826.47
NetD11_1: D11.1 R48.2 | length 66.8
  Top Layer w25: D11.1@1189.8,1826.5 1190.38,1825.92 1190.38,1760.82 R48.2@1190.97,1760.23
NetF1_1: F1.1 J8.2 VSUP.1
  other v2: 3213.9,1688.78 3288.8,1688.78 3366.88,1688.78 3433.28,1688.78 3638.79,1694.02 3366.88,1795.02 3433.28,1795.02 3501.8,1795.02 3575.11,1795.02 3638.79,1800.26 3214.33,1874.46 3289.22,1874.46 3367.31,1874.46 3433.71,1874.46 3639.21,1879.71 3213.9,1954.1 3288.8,1954.1 3366.88,1954.1 3433.28,1954.1 3638.79,1959.35
NetJ6_2: J6.2 S1.1 S1.2 | length 498.4
  Top Layer w15: J6.2@1282,3091.91 1282,3224.46 S1.2@1218.2,3288.26 S1.1@1493.8,3288.26
NetJ9_2: J9.2 R63.1 | length 171.2
  Top Layer w10: R63.1@809.84,4281.55 810.83,4281.55 821.57,4292.3 821.57,4409.32 833.43,4421.17 J9.2@833.43,4442.4
NetJ9_4: J9.4 R62.1 | length 170
  Top Layer w10: J9.4@733.43,4442.4 733.43,4421.25 749.97,4404.7 749.97,4287.91 R62.1@756.08,4281.8
NetJ10_5: J10.5 R66.2 | length 132
  Top Layer w15: J10.5@759,3110.02 765.89,3116.91 765.89,3235.24 R66.2@765.89,3239.18
NetJ10_7: J10.7 R67.2 | length 150.6
  Top Layer w15: J10.7@659,3110.02 659,3188.92 706.9,3236.82 R67.2@706.9,3240.76
NetJ11_1: J11.1 L1.1 | length 83.3
  Top Layer w10: J11.1@1223,4458.01 1223,4421.22 L1.1@1255.92,4388.3
NetJ11_5: J11.5 L2.1 | length 111.9
  Top Layer w10: L2.1@1054.9,4394.86 1091.62,4394.86 1120.64,4423.88 J11.5@1120.64,4458.01
NetP1_23: P1.23 TP39.1 | length 324.3
  Top Layer w10: P1.23@1964.3,3200.7 1984.65,3221.05 TP39.1@2280.18,3221.05
NetP1_25: P1.25 TP40.1 | length 227
  Top Layer w10: P1.25@1964.3,3300.7 2166.93,3300.7 TP40.1@2184.18,3317.95
NetR3_1: R3.1 U4.8 | length 228.5
  Top Layer w15: R3.1@3810.74,1715.13 3849.12,1715.13 3910.91,1776.92 U4.8@3910.91,1879.66
NetR4_2: R4.2 U4.1 | length 3407.8
  Top Layer w15: R4.2@1949.22,4083.82 1949.22,4142.82 v1(1950.22,4143.82) ; v1(4077.04,1880.5) 4124.64,1880.5 U4.1@4125.48,1879.66
  Signal Layer 2 w30: v1(1950.22,4143.82) 1954.2,4147.79 2203.99,4147.79 4077.04,2274.75 v1(4077.04,1880.5)
NetR5_2: R5.2 U5.2 | length 46
  Top Layer w10: R5.2@3121.71,2979.91 3130.61,2988.81 U5.2@3130.61,3021.93 U5.2@3130.79,3021.76
NetTP1_1: TP1.1 U1.22 | length 439.8
  Top Layer w10: v3(357.91,2252.73) 370.02,2264.83 U1.22@421.02,2264.83
  Bottom Layer w10: TP1.1@181.74,1954.01 287.92,2060.19 287.92,2131.56 315.96,2159.6 315.96,2210.78 v3(357.91,2252.73)
NetTP2_1: TP2.1 U1.23 | length 561
  Top Layer w10: U1.23@421.02,2245.15 478.04,2245.15 v3(482.12,2241.07) v3@482.46,2240.74
  Signal Layer 2 w10: TP2.1@182.41,1867.43 230.36,1915.38 230.36,1989.31 v3(482.12,2241.07)
NetTP3_1: TP3.1 U1.21 | length 388.8
  Top Layer w10: v3(368.23,2296.68) 380.4,2284.52 U1.21@421.02,2284.52
  Bottom Layer w10: TP3.1@183.74,2048.59 300.96,2165.81 300.96,2240.4 357.24,2296.68 v3(368.23,2296.68)
NetTP4_1: TP4.1 U1.16 | length 785.3
  Top Layer w10: v1(370,2382) 370.6,2382.6 420.68,2382.6 U1.16@421.02,2382.94
  Bottom Layer w10: TP4.1@184,1765 189,1765 414.59,1990.59 414.59,2337.41 v1(370,2382)
NetTP5_1: TP5.1 U1.88 | length 1744.9
  Top Layer w10: v1(484.01,2655.55) 508.86,2630.7 701.7,2630.7 724.81,2653.81 724.81,2745.79 U1.88@725.16,2746.13
  Signal Layer 1 w15: v1(118.64,2656.13) 117.93,2656.13 90.5,2628.7 90.5,1774.5 139.27,1725.73 TP5.1@184,1681
  Signal Layer 2 w15: v1(118.64,2656.13) 119.53,2655.23 483.7,2655.23 v1(484.01,2655.55)
NetTP6_1: TP6.1 U1.42 | length 930.9
  Top Layer w10: v1(585.12,1972.26) 667.8,1972.26 803.55,2108.01 803.55,2137.52 U1.42@803.9,2137.87
  Bottom Layer w10: TP6.1@184,1602 228.64,1646.64 228.64,1769.13 431.77,1972.26 v1(585.12,1972.26)
nFAULT: P1.1 R24.2 R48.1 TP28.1 U5.4 | length 2831
  Top Layer w10: v1(1191.63,1653) 1516.6,1653 P1.1@1964.3,2100.7 2163.11,2100.7 TP28.1@2184.18,2121.77 ; R24.2@2189.37,2005.19 2189.37,2116.59 TP28.1@2184.18,2121.77 ; U5.4@3169.98,3021.93 3169.98,2813.05 2478.7,2121.77 TP28.1@2184.18,2121.77
  Top Layer w25: R48.1@1190.97,1697.24 1190.97,1653.65 v1(1191.63,1653)
nSLEEP: P1.17 TP36.1 U5.11 | length 1286
  Top Layer w10: P1.17@1964.3,2900.7 1982.83,2919.23 TP36.1@2184.18,2919.23 2279.9,2919.23 2492.84,3132.17 2612,3132.17 2627,3147.17 3096.41,3147.17 3103.22,3153.98 3118.63,3153.98 3130.61,3142 U5.11@3130.61,3132.17
OUT1: C4.2 C5.2 J1.1 TP8.1 U5.6 | length 82.2
  Top Layer w10: U5.6@3195.57,3067.21 3261.51,3067.21 3268.67,3060.04
  Top Layer w30: J1.1@4215.58,2954.35 J1.1@4219.94,2958.72
OUT2: C5.1 C8.2 J1.2 TP10.1 U5.8 | length 61.6
  Top Layer w10: U5.8@3195.57,3106.58 3252.09,3106.58 3255.28,3109.77
  Top Layer w30: J1.2@4219.57,3209.09 J1.2@4219.94,3208.72
PUSH: J6.3 U1.36 | length 1746.2
  Top Layer w10: U1.36@685.79,2137.87 685.79,2323.85 888.76,2526.82 888.76,2528.55 889.5,2529.3 889.5,2580.04 935.12,2625.66 v3(952.51,2625.66)
  Bottom Layer w10: v3(952.51,2625.66) 952.51,2667.77 1066.74,2782.01 1066.74,2878.57 1157.62,2969.45 1164.47,2969.45 1166.34,2971.32 1356.65,2971.32 1409.11,3023.78 1409.11,3049.43 1424.48,3064.8 1424.48,3119.02 1409.11,3134.39 1354.89,3134.39 1339.52,3119.02 1339.52,3064.8 1324.15,3049.43 1299.6,3049.43 1264.4,3049.43 1224.48,3049.43 J6.3@1182,3091.91
RC_OUT: P1.3 R1.2 TP29.1 U5.3 | length 1647.6
  Top Layer w10: P1.3@1964.3,2200.7 1978.07,2214.47 TP29.1@2280.18,2214.47 2550.19,2214.47 3072.24,2736.52 3150.3,2814.58 U5.3@3150.3,3021.93
RC_OUT_DAC: TP7.1 U1.3 | length 237.3
  Top Layer w10: TP7.1@363.7,2828.57 363.7,2655.52 380.38,2638.85 U1.3@421.02,2638.85
RST/SBWTDIO: C41.2 C59.2 J6.1 J10.4 R18.2 R19.1 U1.96 | length 2769.8
  Top Layer w10: U1.96@567.68,2746.13 568.02,2746.48 568.02,2775.99 579.58,2787.55 582.73,2787.55 590.44,2795.26 v1(615.79,2795.26) ; v1(622.19,3058.16) 759.92,3055.36 cw(c759,3010.02) 782.14,3049.03 847.91,3010.02 J10.4@859,3010.02 913.65,3064.66 1063.75,3064.66 v1(1150,3150.91) ; v1(1246.45,3561) 1482.53,3561 1814.69,3893.16 1814.69,3899.07 1874.85,3899.07 R19.1@1874.92,3899.14 ; v1(1331.97,3140.32) 1332.78,3140.32 1381.19,3091.91 J6.1@1382,3091.91 1393.24,3103.15 1496.8,3103.15 C41.2@1519.79,3126.14
  Top Layer w15: R18.2@734.48,2846.49 741.7,2853.7 741.7,2869.83 v1(742.59,2870.73)
  Bottom Layer w10: v1(615.79,2795.26) 613.94,2797.12 613.94,2809.81 613.65,2810.11 613.65,3046.99 622.19,3055.54 v1(622.19,3058.16)
  Bottom Layer w15: v1(615.79,2795.26) 633.14,2795.26 639.85,2801.98 639.85,2806.41 704.17,2870.73 v1(742.59,2870.73) ; v1(1246.45,3561) 1150,3464.55 v1(1150,3150.91) 1320.11,3150.91 1330.71,3140.32 v1(1331.97,3140.32)
SCL: P1.9 R7.2 TP32.1 U5.15 | length 1709.6
  Top Layer w10: R7.2@1689.93,2417.98 1816.31,2544.36 1934.61,2544.36 1964.3,2514.67 P1.9@1964.3,2500.7 1984.1,2520.5 TP32.1@2184.18,2520.5 2252.17,2520.5 2253.25,2519.42 2276.79,2519.42 2824.57,3067.21 U5.15@3085.34,3067.21
SDA: P1.11 R6.2 TP33.1 U5.14 | length 1805.7
  Top Layer w10: R6.2@1624.16,2418.24 1624.16,2466.22 1806.32,2648.37 1916.62,2648.37 P1.11@1964.3,2600.7 1980.7,2617.1 TP33.1@2280.18,2617.1 2345.08,2617.1 2814.87,3086.89 U5.14@3085.34,3086.89
STALL: D10.2 U1.20 | length 782.8
  Top Layer w10: U1.20@421.02,2304.2 464.28,2304.2 v3(480.79,2287.69) ; v3(972.99,1898.07) 981.56,1889.5 D10.2@1032.04,1889.5
  Bottom Layer w10: v3(480.79,2287.69) 870.42,1898.07 v3(972.99,1898.07)
T_RST_RST: R65.1 U2.43 | length 355.5
  Top Layer w10: U2.43@769.03,3582.7 862.66,3489.08 862.66,3353.25 852.41,3343.01 852.41,3324.19 854.47,3322.13 R65.1@818.39,3286.06
T_TEST_TCKC: R64.1 U2.44 | length 375.3
  Top Layer w10: U2.44@778.13,3601.44 924.87,3454.7 R64.1@924.87,3286.91
TST/SBWTCK: J10.2 U1.91 | length 475.4
  Top Layer w10: v1(665.07,2795.96) 666.1,2794.93 U1.91@666.1,2746.13 ; v1(727.58,2816.15) 725.92,2817.81 728.02,2819.91 826,2819.91 v1(945.08,2939) 945.08,2996.1 J10.2@959,3010.02
  Bottom Layer w10: v1(665.07,2795.96) 688.58,2819.47 716.99,2819.47 723.94,2812.52 v1(727.58,2816.15)
USB_D_N: J11.2 R72.1 U6.3 | length 622.1
  Top Layer w10: v1(1133.79,4246) 1167.94,4211.85 R72.1@1167.94,4125.19 ; U6.3@1183.4,4333.77 1183.4,4321.14 1183.72,4320.82 ; J11.2@1197.41,4458.01 1197.95,4457.46 1197.95,4391.43 1202.18,4387.2 1202.18,4339.28 1183.72,4320.82 ; v1(1222,4223) 1183.72,4261.28 1183.72,4320.82
  Bottom Layer w10: v1(1112.46,4353) 1112.46,4267.33 v1(1133.79,4246) 1199,4246 v1(1222,4223)
USB_D_P: J11.3 R75.1 U6.2 U6.5 U6.6 | length 390.1
  Top Layer w10: J11.3@1171.82,4458.01 1171.82,4413.6 1166.39,4408.17 1165.83,4408.17 1144.03,4386.38 U6.6@1144.03,4357.39 U6.5@1163.72,4357.39 U6.2@1163.72,4333.77 1163.72,4249.16 1216.37,4196.5 R75.1@1216.37,4121.26
VM: C1.2 C6.1 C55.1 C56.2 C57.2 C58.2 D4.2 F1.2 R3.2 R12.2 U5.5 VM.1 | length 385.4
  Top Layer w10: R12.2@3670.94,2255.83 3670.94,2218.18 3702.9,2186.22 D4.2@3741.15,2186.22
  Top Layer w15: 3718.99,1961.7 3718.99,1887.13 3715.87,1884 3715.87,1813.74 3752.46,1777.14 3752.46,1718.28 R3.2@3755.62,1715.13
  other v2: 3225.43,2047.67 3304.72,2047.67 3384.01,2047.67 3463.31,2047.67 3542.6,2047.67 3621.89,2047.67 3701.18,2047.67 3502.21,2106.9 3585.27,2106.9 3225.56,2113.56 3304.86,2113.56 3384.15,2113.56 3701.18,2143.85 3463.31,2166.52 3542.6,2166.52 3621.89,2166.52 3621.89,2220.17 3236.18,2260.81 3315.48,2260.81 3394.77,2260.81 3225.56,2321.87 3484.21,2360.23 3280.2,2437.66 3339.88,2487.6 3269.71,2537.2
VREF: P1.7 TP31.1 U5.16 | length 1389
  Top Layer w10: P1.7@1964.3,2400.7 1979.39,2415.79 TP31.1@2280.18,2415.79 2342.62,2415.79 2974.35,3047.52 U5.16@3085.34,3047.52
VSEN_VM: C60.2 R12.1 R35.2 U1.97 | length 5068.4
  Top Layer w10: U1.97@547.99,2746.13 548.34,2745.79 548.34,2709.28 576.78,2680.85 v1(577.59,2680.85) ; v1@848,2791 848,2803.8 v1(1112.91,3068.71) ; v1@1186,3540 1235.32,3540 1237.04,3538.28 1493.49,3538.28 v1(1782.91,3827.71) ; C60.2@2136,3880.11 2147.11,3869 R35.2@2196,3869 ; v1(2196,3826) 2196,3867 R35.2@2197,3868
  Top Layer w15: R12.1@3715.48,2300.38 3780.55,2300.38 v1(3780.96,2299.96)
  Signal Layer 2 w15: v1@1783,3828 1785,3826 v1(2196,3826) 2254.92,3826 v1(3780.96,2299.96)
  Bottom Layer w10: v1(577.59,2680.85) 577.59,2530.5 592.81,2515.28 636.85,2515.28 696.23,2574.67 696.23,2640.23 v1(849,2793)
  Bottom Layer w15: v1@1111.04,3069 1112.91,3070.87 1112.91,3466.71 v1(1184.91,3538.71)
